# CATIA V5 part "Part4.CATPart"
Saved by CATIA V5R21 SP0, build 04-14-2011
Part number: Part4
Bounding box of the stored display mesh (mm): x 0 to 0, y -64.995 to 64.997, z -62.397 to 61.983
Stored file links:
  C:\Users\RIAD MAHAMUD PIASH\Desktop\Part4.CATPart
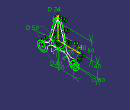
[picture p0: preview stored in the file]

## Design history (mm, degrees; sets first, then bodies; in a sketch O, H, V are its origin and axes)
Body1 (main body)
  Sketch1 on yz-plane, origin (0, 0, 0), H (0, 1, 0), V (0, 0, 1)
    arc A1 centre (0, 0) radius 20 from (-20, 0) to (20, 0) ccw
    arc A2 centre (0, 0) radius 25 from (-25, 0) to (-24.815, -3.0356) ccw
    arc A3 centre (50, -40) radius 15 from (35.0282, -40.92) to (47.611, -25.1915) ccw
    point P1 (50, -40)
    circle A4 centre (50, -40) radius 10
    arc A5 centre (-50, -40) radius 15 from (-35.0282, -40.92) to (-47.611, -25.1915) cw
    circle A6 centre (-50, -40) radius 10
    arc A7 centre (0, 50) radius 12 from (11.6349, 52.9375) to (-11.6349, 52.9375) ccw
    point P3 (0, 50)
    point P4 (35.0282, -40.92)
    arc A8 centre (15.0829, -42.397) radius 20 from (35.0282, -40.92) to (8.4088, -23.5434) ccw
    point P6 (8.4088, -23.5434)
    point P7 (24.815, -3.0356)
    point P8 (47.611, -25.1915)
    arc A9 centre (44.6738, -5.4083) radius 20 from (47.611, -25.1915) to (24.815, -3.0356) cw
    point P10 (-8.4088, -23.5434)
    point P11 (-35.0282, -40.92)
    arc A10 centre (-15.0829, -42.397) radius 20 from (-35.0282, -40.92) to (-8.4088, -23.5434) cw
    point P13 (-24.815, -3.0356)
    point P14 (-47.611, -25.1915)
    arc A11 centre (-44.6738, -5.4083) radius 20 from (-47.611, -25.1915) to (-24.815, -3.0356) ccw
    line L1 (-25, 0) -> (-11.6349, 52.9375)
    point P16 (-25, 0)
    point P17 (-11.6349, 52.9375)
    point P18 (11.6349, 52.9375)
    point P19 (25, 0)
    line L2 (25, 0) -> (11.6349, 52.9375)
    line L3 (-20, 0) -> (-4.8518, 51.2249)
    point P20 (-20, 0)
    point P21 (-4.8518, 51.2249)
    point P22 (4.8518, 51.2249)
    point P23 (20, 0)
    line L4 (20, 0) -> (4.8518, 51.2249)
    arc A12 centre (0, 50) radius 5 from (4.957, 50.6544) to (-4.8479, 51.2238) ccw
    arc A13 centre (0, 0) radius 25 from (-8.4088, -23.5434) to (8.4088, -23.5434) ccw
    arc A14 centre (0, 0) radius 25 from (24.815, -3.0356) to (25, 0) ccw
    radius A2 = 25
    radius A1 = 20
    radius A3 = 15
    radius A4 = 10
    distance P1 H = 40
    distance P1 V = 50
    radius A7 = 12
    distance P3 H = 50
    radius A8 = 20
    symmetry: A3 A5 V, A4 A6 V, P6 P10 V, P4 P11 V, A8 A10 V, P7 P13 V, P8 P14 V, A9 A11 V, P17 P18 V, P16 P19 V, L1 L2 V, P21 P22 V, P20 P23 V, L3 L4 V
    coincidence: P3 V, P6 A2, P16 H, P20 H, A2 A13, A13 A14
    tangency: L1 A7, A12 L3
